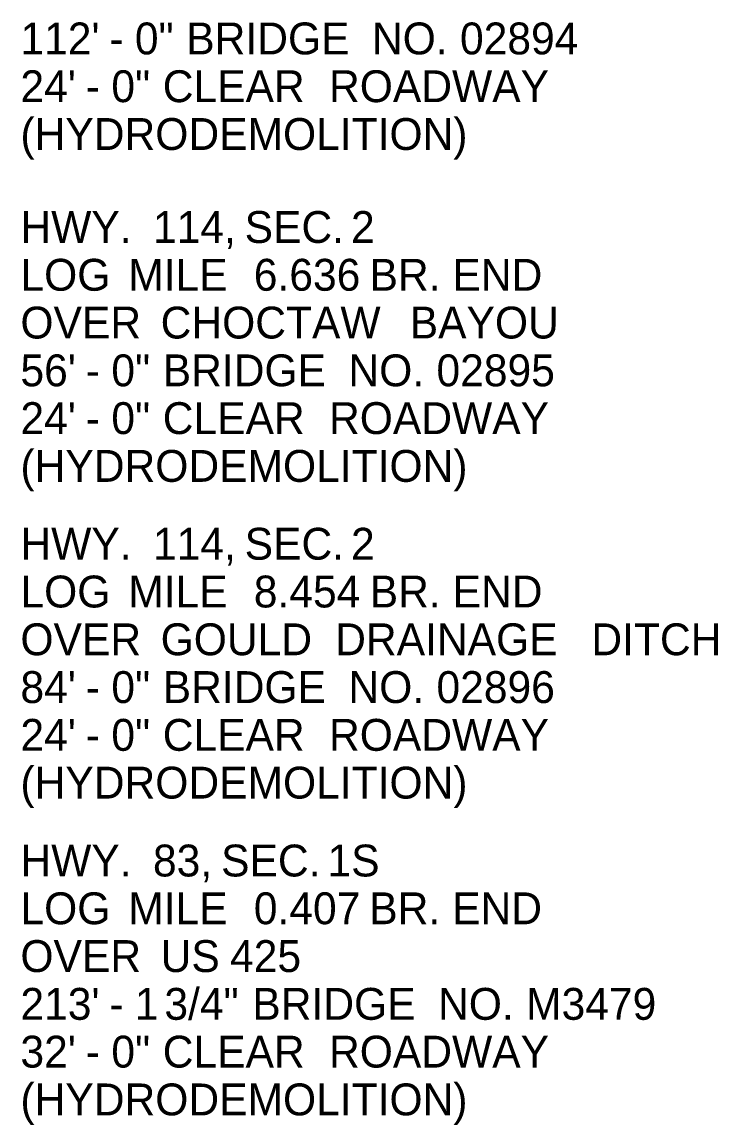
# Model space of a CAD drawing. Extents: x -33639 to 34530, y -17264 to 5867.
# Drawn here: x -5603 to -3964, y -14942 to -12345 of the extents above; entities that cross this region are included whole.
import ezdxf

# ---------------------------------------------------------------- set-up
doc = ezdxf.new("R2010")
doc.units = 0
doc.layers.add('Default', color=7, linetype='Continuous')

msp = doc.modelspace()

# ---------------------------------------------------------------- texts
at = {"layer": 'Default'}
for s, p in [("112'", (-5606.6, -12421.5)), (' 0"', (-5364.9, -12421.5)), (' BRIDGE', (-5243.9, -12421.5)), (' NO.', (-4806.5, -12421.5)), (' 02894', (-4599.1, -12421.5)), (' -', (-5425.1, -12421.5)), ("24'", (-5606.6, -12534)), (' 0"', (-5420.3, -12534)), (' CLEAR', (-5299.3, -12534)), (' ROADWAY', (-4907.6, -12534)), (' -', (-5480.5, -12534)), ('(HYDRODEMOLITION)', (-5606.6, -12646.5)), ('HWY.', (-5606.6, -12865.5)), (' 114,', (-5322.3, -12865.5)), (' SEC.', (-5106.3, -12865.5)), (' 2', (-4855.8, -12865.5)), ('LOG', (-5606.6, -12978)), (' MILE', (-5380.6, -12978)), (' 6.636', (-5084.8, -12978)), (' BR.', (-4812.1, -12978)), (' END', (-4616.9, -12978)), ('OVER', (-5606.6, -13090.5)), (' CHOCTAW', (-5304.2, -13090.5)), (' BAYOU', (-4717.5, -13090.5)), ("56'", (-5606.6, -13203)), (' 0"', (-5420.3, -13203)), (' BRIDGE', (-5299.3, -13203)), (' NO.', (-4861.9, -13203)), (' 02895', (-4654.5, -13203)), (' -', (-5480.5, -13203)), ("24'", (-5606.6, -13315.5)), (' 0"', (-5420.3, -13315.5)), (' CLEAR', (-5299.3, -13315.5)), (' ROADWAY', (-4907.6, -13315.5)), (' -', (-5480.5, -13315.5)), ('(HYDRODEMOLITION)', (-5606.6, -13428)), ('HWY.', (-5606.6, -13611.3)), (' 114,', (-5322.3, -13611.3)), (' SEC.', (-5106.3, -13611.3)), (' 2', (-4855.8, -13611.3)), ('LOG', (-5606.6, -13723.8)), (' MILE', (-5380.6, -13723.8)), (' 8.454', (-5084.8, -13723.8)), (' BR.', (-4811.7, -13723.8)), (' END', (-4616.5, -13723.8)), ('OVER', (-5606.6, -13836.3)), (' GOULD', (-5304.2, -13836.3)), (' DRAINAGE', (-4893.1, -13836.3)), (' DITCH', (-4289.7, -13836.3)), ("84'", (-5606.6, -13948.8)), (' 0"', (-5420.3, -13948.8)), (' BRIDGE', (-5299.3, -13948.8)), (' NO.', (-4861.9, -13948.8)), (' 02896', (-4654.5, -13948.8)), (' -', (-5480.5, -13948.8)), ("24'", (-5606.6, -14061.3)), (' 0"', (-5420.3, -14061.3)), (' CLEAR', (-5299.3, -14061.3)), (' ROADWAY', (-4907.6, -14061.3)), (' -', (-5480.5, -14061.3)), ('(HYDRODEMOLITION)', (-5606.6, -14173.8)), ('HWY.', (-5606.6, -14357.2)), (' 83,', (-5322.3, -14357.2)), (' SEC.', (-5161.8, -14357.2)), (' 1S', (-4911.2, -14357.2)), ('LOG', (-5606.6, -14469.7)), (' MILE', (-5380.6, -14469.7)), (' 0.407', (-5084.8, -14469.7)), (' BR.', (-4812.8, -14469.7)), (' END', (-4617.6, -14469.7)), ('OVER', (-5606.6, -14582.2)), (' US', (-5304.2, -14582.2)), (' 425', (-5140.7, -14582.2)), ("213'", (-5606.6, -14694.7)), (' 1', (-5364.9, -14694.7)), (' 3/4"', (-5295.4, -14694.7)), (' BRIDGE', (-5088.2, -14694.7)), (' NO.', (-4650.8, -14694.7)), (' M3479', (-4443.4, -14694.7)), (' -', (-5425.1, -14694.7)), ("32'", (-5606.6, -14807.2)), (' 0"', (-5420.3, -14807.2)), (' CLEAR', (-5299.3, -14807.2)), (' ROADWAY', (-4907.6, -14807.2)), (' -', (-5480.5, -14807.2)), ('(HYDRODEMOLITION)', (-5606.6, -14919.7))]:
    msp.add_text(s, height=75, dxfattribs=at).set_placement(p)

doc.saveas('drawing.dxf')
